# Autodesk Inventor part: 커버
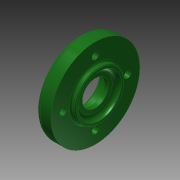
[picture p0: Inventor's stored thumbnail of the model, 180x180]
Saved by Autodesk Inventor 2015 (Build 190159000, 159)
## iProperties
Created: 2015-11
Part Number: 커버
Material: 알루미늄 6061
Document SubType Name: Modeling
Designer: mduedu
Density: 2.71 g/cm^3
Mass: 57.8273 g
Surface Area: 81.1807 cm^2
Volume: 21.3385 cm^3
Appearance: 매끄러움 - 짙은 산림 녹색
Author: mduedu
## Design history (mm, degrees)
sketch "스케치1"
  geometry: L1 (-6.5, 0)-(6.5, 0); L2 (-6.5, 0)-(-6.5, 29); L3 (-6.5, 29)-(3.5, 29); L4 (3.5, 29)-(3.5, 16); L5 (3.5, 16)-(6.5, 16); L6 (6.5, 16)-(6.5, 0); 2 further points
  constraints: 12 end point, 3 perpendicular, 2 parallel, 1 coincident, 1 horizontal, 1 midpoint
  dimensions: "d0" = 13 distance of L1.start L1.end; "d1" = 58 diameter of L3 L1; "d2" = 3 distance of L4.end L5.end; "d3" = 32 diameter of L5 L1
revolve "회전1" sketch "스케치1" stored, may be unused: angle "d4" = 90 deg
hole "구멍1" diameter "d7" = 28; stored, may be unused: countersink angle "d11" = 90 deg, drill point angle "d13" = 0 deg; dims "d8" = 6, "d9" = 4, "d10" = 2, "d12" = 3, "d65" = 10, "d66" = 10
hole "구멍2" diameter "d16" = 25; stored, may be unused: countersink angle "d20" = 90 deg, drill point angle "d22" = 0 deg; dims "d17" = 6, "d18" = 4, "d19" = 2, "d21" = 7.3, "d67" = 10, "d68" = 10
hole "구멍3" diameter "d25" = 17; stored, may be unused: countersink angle "d29" = 90 deg, drill point angle "d31" = 0 deg; dims "d23" = 10, "d24" = 10, "d26" = 6, "d27" = 4, "d28" = 2, "d30" = 4.2
chamfer "모따기1" distance "d32" = 0.7; stored, may be unused: second distance "d33" = 2, angle "d34" = 30 deg
fillet "모깎기1" dims "d35" = 0.2
fillet "모깎기2" dims "d36" = 3
fillet "모깎기3" dims "d37" = 3
fillet "모깎기4" dims "d38" = 1
sketch "스케치3" dims "d61" = 42
  geometry: C1 r 29 at (0, 0) reference; 2 further points
  constraints: 2 vertical alignment, 1 coincident, 2 other
hole "구멍4" sketch "스케치3" at (0, -21) diameter "d44" = 4.5; stored, may be unused: countersink angle "d48" = 90 deg, drill point angle "d50" = 0 deg; dims "d45" = 6, "d46" = 8, "d47" = 4.6, "d49" = 8
chamfer "모따기2" distance "d62" = 0.5; stored, may be unused: second distance "d63" = 2, angle "d64" = 45 deg
node "솔리드1"
pattern_circular "원형 패턴1" dims angle "d54" = 360 deg
